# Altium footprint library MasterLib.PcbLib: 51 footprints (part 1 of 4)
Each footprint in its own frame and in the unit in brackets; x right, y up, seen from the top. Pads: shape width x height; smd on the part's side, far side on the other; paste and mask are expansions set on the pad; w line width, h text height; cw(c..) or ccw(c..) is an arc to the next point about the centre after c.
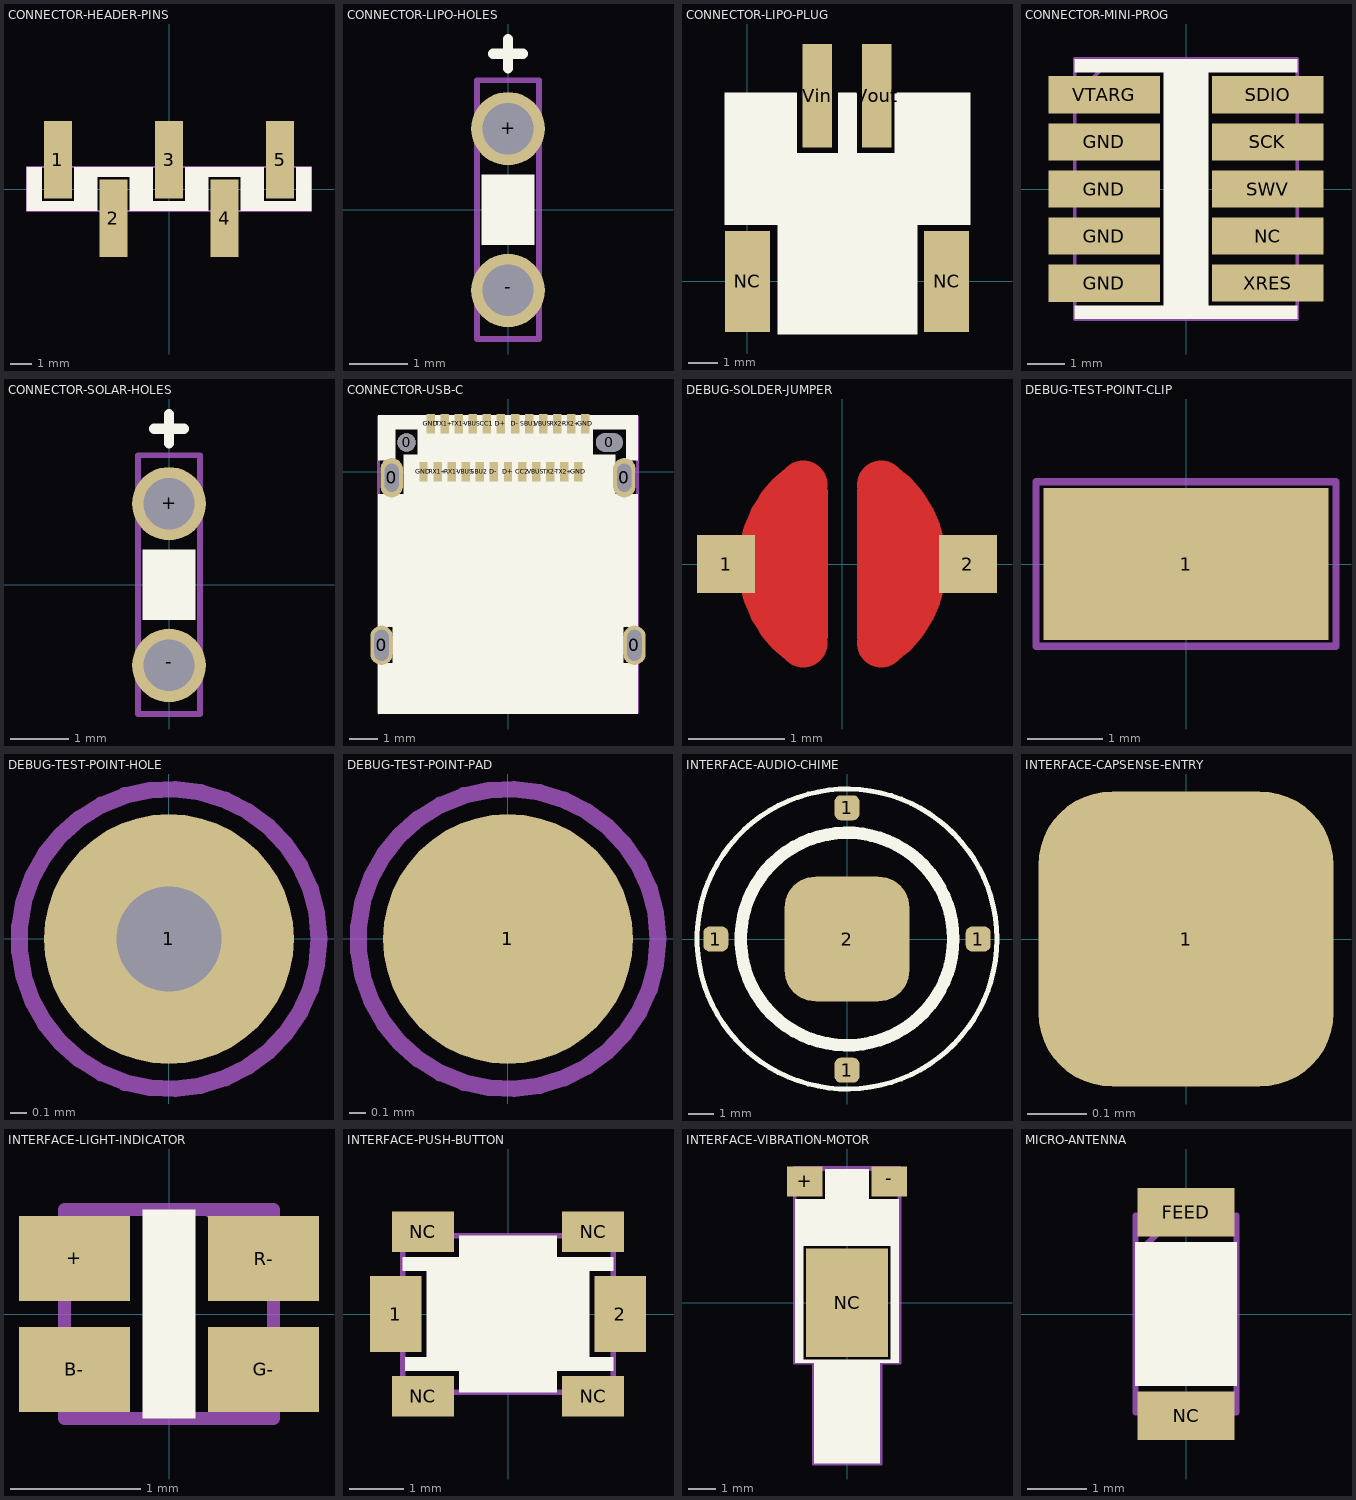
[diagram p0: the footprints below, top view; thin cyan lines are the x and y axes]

## CONNECTOR-HEADER-PINS [mm]
pads (5):
  rect 1.27x3.56 smd: 1(-5.08,1.335) 2(-2.54,-1.335) 3(0,1.335) 4(2.54,-1.335) 5(5.08,1.335)
Top Overlay:
  region: -6.5,1 -5.825,1 -5.825,-0.55 -4.325,-0.55 -4.325,1 -0.75,1 -0.75,-0.55 0.75,-0.55 0.75,1 4.325,1 4.325,-0.55 5.825,-0.55 5.825,1 6.5,1 6.5,-1 3.275,-1 3.275,0.55 1.8,0.55 1.8,-1 -1.8,-1 -1.8,0.55 -3.275,0.55 -3.275,-1 -6.5,-1
Assembly Top:
  lines w0.1: -6.5,0.5 -6,1 ; -6.5,-1 -6.5,1 6.5,1 6.5,-1 -6.5,-1
  text ".Designator" at -0.6,-0.2 h0.4
3D body "CONNECTOR-HEADER-PINS.step": height 9.78, standoff 0.04, extent -6.07,-2.56 6.22,2.32

## CONNECTOR-LIPO-HOLES [mil]
pads (2):
  round 50 hole 35 paste-3937.01: +(0,55) -(0,-55)
Top Overlay:
  rectangle: -18,-24 18,24
  lines w7: -10,106 0,106 10,106 ; 0,96 0,116
Assembly Top:
  lines w3.94: -21,-88 -21,88 21,88 21,-88 -21,-88
  text ".Designator" at -5,20 h15.75
  text "+" at -13,86 h39.37
  text "-" at -21,-88 h39.37

## CONNECTOR-LIPO-PLUG [mm]
pads (4):
  rect 1.5x3.4 smd: NC(0,0) NC(6.7,0)
  rect 1x3.5 smd: Vin(2.35,6.25) Vout(4.35,6.25)
Top Overlay:
  region: 5.715,-1.778 5.715,1.905 7.493,1.905 7.493,6.35 4.953,6.35 4.953,4.318 3.683,4.318 3.683,6.35 3.048,6.35 3.048,4.318 1.651,4.318 1.651,6.35 -0.762,6.35 -0.762,1.905 1.016,1.905 1.016,-1.778
Assembly Top:
  text "-" at 4.35,-0.762 h1.52
  text "+" at 1.372,-0.762 h1.52
3D body: height 0.25, standoff 0, extent -1.067,7.163 -1.067,7.163
3D body: height 0.25, standoff 0, extent -1.676,6.858 -1.676,6.858
3D body "CONNECTOR-LIPO-PLUG.step": height 5.5, standoff 0, extent -0.585,-1.59 7.315,7.01

## CONNECTOR-MINI-PROG [mm]
pads (10):
  rect 3x1 smd: GND(-2.2,-2.54) GND(-2.2,-1.27) GND(-2.2,0) GND(-2.2,1.27) NC(2.2,-1.27) SCK(2.2,1.27) SDIO(2.2,2.54) SWV(2.2,0) VTARG(-2.2,2.54) XRES(2.2,-2.534)
Top Overlay:
  region: 3,3.5 3,3.15 0.6,3.15 0.6,-3.15 3,-3.15 3,-3.5 -3,-3.5 -3,-3.15 -0.6,-3.15 -0.6,3.15 -3,3.15 -3,3.5
Assembly Top:
  lines w0.1: -3,2.5 -2,3.5 ; -3,-3.5 3,-3.5 3,3.5 -3,3.5 -3,-3.5
  text ".Designator" at -0.6,-0.2 h0.4
3D body "CONNECTOR-MINI-PROG.step": height 6.1, standoff -0.03, extent -2.949,-3.193 2.893,3.157

## CONNECTOR-SOLAR-HOLES [mil]
pads (2):
  round 50 hole 35 paste-3937.01: +(0,55) -(0,-55)
Top Overlay:
  rectangle: -18,-24 18,24
  lines w7: -10,106 0,106 10,106 ; 0,96 0,116
Assembly Top:
  lines w3.94: -21,-88 21,-88 21,88 -21,88 -21,-88
  text "-" at -21,-88 h39.37
  text "+" at -13,86 h39.37
  text ".Designator" at -5,20 h15.75

## CONNECTOR-USB-C [mm]
pads (30):
  oval 0.8x1.4 hole 1.1 slot 0.5 at 0 deg: 0(-4.49,-6.16) 0(4.49,-6.16)
  oval 0.8x1.4 hole 1 slot 0.5 at 0 deg: 0(-4.13,-0.21) 0(4.13,-0.21)
  round 0.65 hole 0.65 unplated: 0(-3.6,1.04)
  oval 0.95x0.65 hole 0.65 slot 0.95 at 0 deg unplated: 0(3.6,1.04)
  rect 0.3x0.7 smd: CC1(-0.75,1.7) CC2(0.5,0) D+(-0.25,1.7) D+(0,0) D-(-0.5,0) D-(0.25,1.7) GND(-3,0) GND(-2.75,1.7) GND(2.5,0) GND(2.75,1.7) RX1+(-2.5,0) RX1-(-2,0) RX2+(2.25,1.7) RX2-(1.75,1.7) SBU1(0.75,1.7) SBU2(-1,0) TX1+(-2.25,1.7) TX1-(-1.75,1.7) TX2+(2,0) TX2-(1.5,0) VBUS(-1.5,0) VBUS(-1.25,1.7) VBUS(1,0) VBUS(1.25,1.7)
Top Overlay:
  region: -4.6,-8.55
  region: -4.6,-6.8 -4.1,-6.8 -4.1,-5.5 -4.6,-5.5 -4.6,-0.8 -3.7,-0.8 -3.7,0.6 -3.2,0.6 -3.2,1.5 -4,1.5 -4,0.4 -4.6,0.4 -4.6,2 4.6,2 4.6,0.4 4.2,0.4 4.2,1.5 3,1.5 3,0.6 3.8,0.6 3.8,-0.8 4.6,-0.8 4.6,-5.5 4.1,-5.5 4.1,-6.8 4.6,-6.8 4.6,-8.6 -4.6,-8.6
Assembly Top:
  lines w0.1: -4.6,-8.55 4.6,-8.55 4.6,1.95 -4.6,1.95 -4.6,-8.55
  text "USB C" at -0.9,-0.2 h0.4
3D body "12401598E4#2A.stp": height 3.17, standoff -2.21, extent -4.6,-8.594 4.6,1.956

## DEBUG-SOLDER-JUMPER [mm]
pads (2):
  rect 0.6x0.6 smd paste-1: 1(-1.202,0) 2(1.3,0)
Top Layer:
  region: -0.152,0.77 -0.829,0.5 -0.829,-0.5 -0.152,-0.77
  region: 0.152,-0.77 0.829,-0.5 0.829,0.5 0.152,0.77
  lines w0.5: -0.402,-0.819 cw(c0.171,0) -0.402,0.819 ; 0.402,-0.819 ccw(c-0.171,0) 0.402,0.819
Assembly Top:
  text ".Designator" at -0.6,-0.2 h0.4

## DEBUG-TEST-POINT-CLIP [mm] "Keystone, 5019"
height 4.57
pads (1):
  rect 3.8x2.03 smd: 1(0,0)
Assembly Top:
  lines w0.1: -2,-1.1 -2,1.1 2,1.1 2,-1.1 -2,-1.1
  text ".Designator" at -0.6,-0.2 h0.4
3D body "DEBUG-TEST-POINT-CLIP.step": height 2.3, standoff 0.01, extent -1.905,-1.045 1.905,0.985

## DEBUG-TEST-POINT-HOLE [mm]
height 4.57
pads (1):
  round 1.5 hole 0.63 paste-1: 1(0,0)
Assembly Top:
  circle w0.1: c0,0 r0.9
  text ".Designator" at -0.6,-0.2 h0.4

## DEBUG-TEST-POINT-PAD [mm]
height 4.57
pads (1):
  round 1.5 smd paste-1: 1(0,0)
Assembly Top:
  circle w0.1: c0,0 r0.9
  text ".Designator" at -0.6,-0.2 h0.4

## INTERFACE-AUDIO-CHIME [mm]
pads (5):
  rrect50% 1x1 smd: 1(-5.25,0) 1(0,-5.25) 1(0,5.25) 1(5.25,0)
  rrect50% 5x5 smd: 2(0,0)
Top Overlay:
  circle w0.5: c0,0 r4.25
  circle w0.2: c0,0 r6
Assembly Top:
  circle w0.1: c0,0 r6
  text ".Designator" at -0.6,-0.2 h0.4
3D body "INTERFACE-AUDIO-CHIME.step": height 0.24, standoff 0.03, extent -5.995,-5.937 6.005,6.063

## INTERFACE-CAPSENSE-ENTRY [mm]
pads (1):
  rrect50% 0.5x0.5 smd paste+0 mask+0: 1(0,0)
Assembly Top:
  text ".Designator" at -0.4,-0.2 h0.4

## INTERFACE-LIGHT-INDICATOR [mm]
height 1.8
pads (4):
  rect 0.85x0.65 smd: +(-0.725,0.425) B-(-0.725,-0.425) G-(0.725,-0.425) R-(0.725,0.425)
Top Overlay:
  region: -0.2,0.8 0.2,0.8 0.2,-0.8 -0.2,-0.8
Assembly Top:
  lines w0.1: 0.3,0.8 0.8,0.4 ; -0.8,-0.8 -0.8,0.8 0.8,0.8 0.8,-0.8 -0.8,-0.8
  text ".Designator" at -0.4,-0.2 h0.4
3D body "INTERFACE-LIGHT-INDICATOR.step": height 0.27, standoff -0.08, extent -0.806,-0.794 0.794,0.806

## INTERFACE-PUSH-BUTTON [mm]
pads (6):
  rect 0.95x1.4 smd: 1(-2.075,0) 2(2.075,0)
  rect 1.15x0.75 smd: NC(-1.575,-1.525) NC(-1.575,1.525) NC(1.575,-1.525) NC(1.575,1.525)
Top Overlay:
  region: -0.9,1.45 0.9,1.45 0.9,1.05 1.95,1.05 1.95,0.8 1.5,0.8 1.5,-0.8 1.95,-0.8 1.95,-1.05 0.9,-1.05 0.9,-1.45 -0.9,-1.45 -0.9,-1.05 -1.9,-1.05 -1.9,-0.8 -1.5,-0.8 -1.5,0.8 -1.95,0.8 -1.95,1.05 -0.9,1.05
Assembly Top:
  lines w0.1: -1.95,-1.45 -1.95,1.45 1.95,1.45 1.95,-1.45 -1.95,-1.45
  text ".Designator" at -0.6,-0.2 h0.4
3D body "INTERFACE-PUSH-BUTTON.step": height 1.82, standoff -0.04, extent -2.207,-1.455 2.293,1.507

## INTERFACE-VIBRATION-MOTOR [mm]
pads (3):
  rect 1.3x1.1 smd: +(-1.55,4.45) -(1.55,4.45)
  rect 3x4 smd: NC(0,0)
Top Overlay:
  region: -1.6,-2.1 1.6,-2.1 1.6,-2.2 -1.6,-2.2
  region: -1.2,-2.2 1.2,-2.2 1.2,-5.9 -1.2,-5.9
  region: -0.8,4.9 0.8,4.9 0.8,3.8 1.9,3.8 1.9,-2.2 1.6,-2.2 1.6,2.1 -1.6,2.1 -1.6,-2.2 -1.9,-2.2 -1.9,3.8 -0.8,3.8
Assembly Top:
  lines w0.1: -1.942,-2.23 -1.242,-2.23 -1.242,-5.93 1.258,-5.93 1.258,-2.23 1.958,-2.23 1.958,4.97 -1.942,4.97 -1.942,-2.23 ; -1.9,-2.2 -1.9,4.9 1.9,4.9 1.9,-2.2 1.2,-2.2 1.2,-5.9 -1.2,-5.9 -1.2,-2.2 -1.9,-2.2
  text ".Designator" at 0.2,-0.6 h0.4
3D body "INTERFACE-VIBRATION-MOTOR.step": height 3.1, standoff -0.05, extent -2.05,-5.857 2.05,4.943

## MICRO-ANTENNA [mil]
height 55.12
pads (2):
  rect 64x32 smd: FEED(0,67) NC(0,-67)
Top Overlay:
  region: -33.46,47.24 33.46,47.24 33.46,-47.24 -33.46,-47.24
Assembly Top:
  lines w3.94: -33.46,38.39 -7.87,63.98 ; -33.46,-64.96 -33.46,64.96 33.46,64.96 33.46,-64.96 -33.46,-64.96
  text ".Designator" at 7.87,-23.62 h15.75
3D body "MICRO-ANTENNA.step": height 48.07, standoff -3.11, extent -33.47,-62.99 33.46,63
